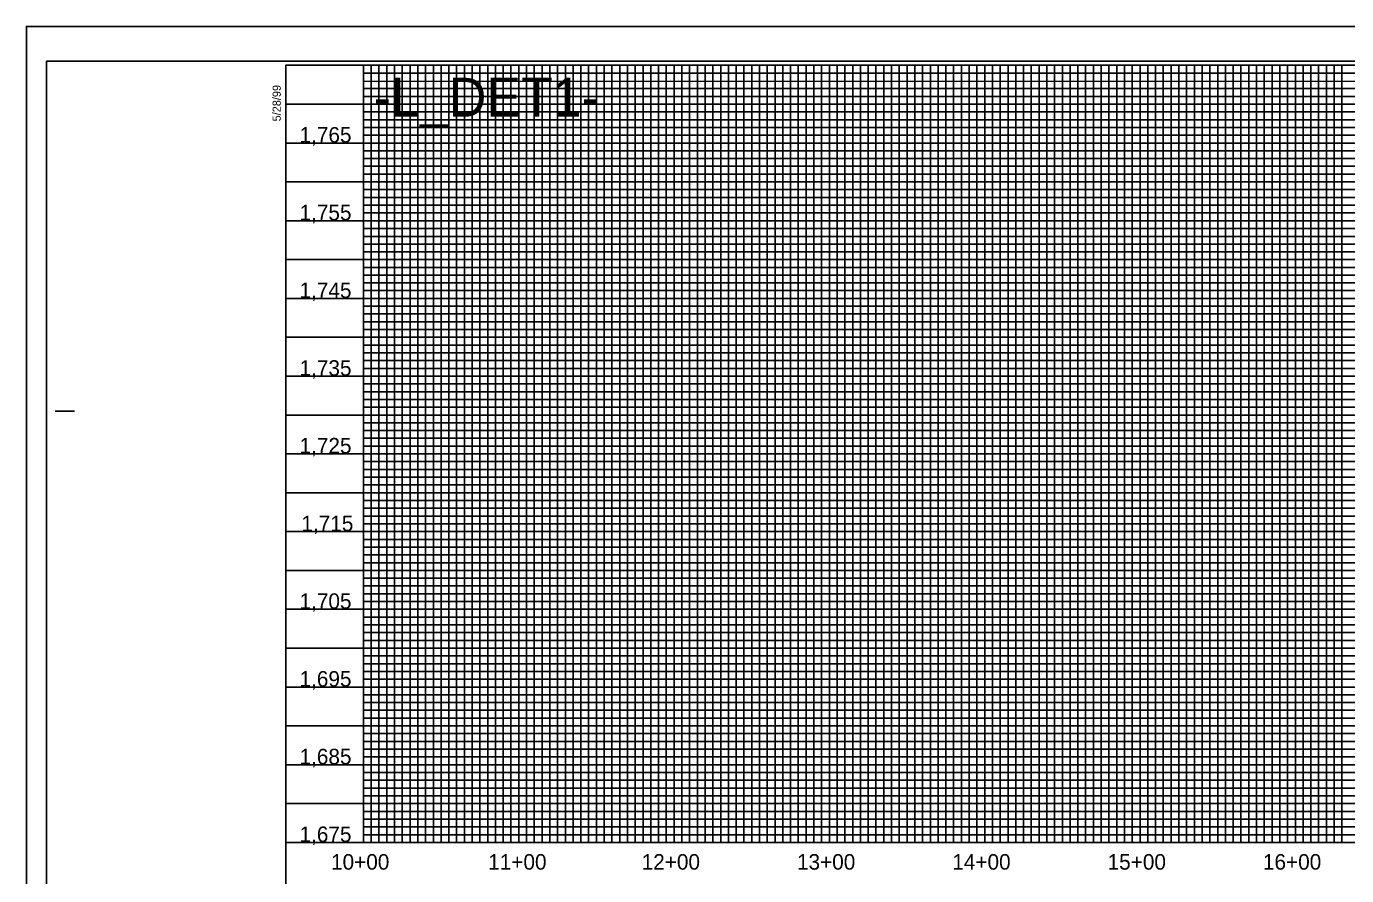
# Model space of a CAD drawing. Extents: x 505692 to 507376, y 438761 to 439861.
# Drawn here: x 505692 to 506542, y 439315 to 439861 of the extents above; entities that cross this region are included whole.
import ezdxf

# ---------------------------------------------------------------- set-up
doc = ezdxf.new("R2010")
doc.units = 0
for name, color, linetype in [('Exist Vertical Profile Vertical Axis Label', 7, 'Continuous'), ('Old_Level_1', 7, 'Continuous'), ('Prop Grid Mask', 7, 'Continuous'), ('Sheet Cutting Line CELL', 7, 'Continuous'), ('Sheet DOT Grid CELL', 7, 'Continuous'), ('Sheet Layout Profile Border Port 1', 7, 'Continuous'), ('Sheet Plot Border Inside CELL', 7, 'Continuous'), ('Sheet Plot Border Outside CELL', 7, 'Continuous'), ('Sheet Profile CELL', 7, 'Continuous'), ('Sheet Profile Grid Major CELL', 7, 'Continuous'), ('Sheet Profile Grid Middle CELL', 7, 'Continuous'), ('Sheet Profile Grid Minor CELL', 7, 'Continuous')]:
    doc.layers.add(name, color=color, linetype=linetype)

msp = doc.modelspace()

# ---------------------------------------------------------------- linework, layer by layer
at = {"layer": 'Prop Grid Mask'}
msp.add_lwpolyline([(506068.68, 439836.14), (505908.68, 439836.14), (505908.68, 439791.14), (506068.68, 439791.14)], close=True, dxfattribs=at)
at = {"layer": 'Sheet Cutting Line CELL'}
for p, q in [((507375.68, 439861.14), (505691.68, 439861.14)), ((505691.68, 439861.14), (505691.68, 438761.14))]:
    msp.add_line(p, q, dxfattribs=at)
at = {"layer": 'Sheet DOT Grid CELL'}
for p, q in [((505908.68, 439336.14), (505908.68, 439836.14)), ((505958.68, 439336.14), (505958.68, 439836.14)), ((506008.68, 439336.14), (506008.68, 439836.14)), ((506058.68, 439336.14), (506058.68, 439836.14)), ((506108.68, 439336.14), (506108.68, 439836.14)), ((506158.68, 439336.14), (506158.68, 439836.14)), ((506208.68, 439336.14), (506208.68, 439836.14)), ((506258.68, 439336.14), (506258.68, 439836.14)), ((506308.68, 439336.14), (506308.68, 439836.14)), ((506358.68, 439336.14), (506358.68, 439836.14)), ((506408.68, 439336.14), (506408.68, 439836.14)), ((506458.68, 439336.14), (506458.68, 439836.14)), ((506508.68, 439336.14), (506508.68, 439836.14)), ((507158.63, 439786.14), (505858.68, 439786.14)), ((507158.63, 439736.14), (505858.68, 439736.14)), ((507158.68, 439686.14), (505858.68, 439686.14)), ((507358.68, 439636.14), (505858.68, 439636.14)), ((507358.68, 439586.14), (505858.68, 439586.14)), ((507358.68, 439536.14), (505858.68, 439536.14)), ((507358.68, 439486.14), (505858.68, 439486.14)), ((507358.68, 439436.14), (505858.68, 439436.14)), ((507358.68, 439386.14), (505858.68, 439386.14))]:
    msp.add_line(p, q, dxfattribs=at)
at = {"layer": 'Sheet Layout Profile Border Port 1'}
msp.add_lwpolyline([(505908.68, 439836.14), (505908.68, 439336.14), (507108.68, 439336.14), (507108.68, 439486.14), (507108.68, 439636.14), (507108.68, 439836.14)], close=True, dxfattribs=at)
at = {"layer": 'Sheet Plot Border Inside CELL'}
msp.add_lwpolyline([(505704.68, 438783.59), (507371.18, 438783.59), (507371.18, 439838.69), (505704.68, 439838.69)], close=True, dxfattribs=at)
at = {"layer": 'Sheet Plot Border Outside CELL'}
msp.add_lwpolyline([(505691.68, 438761.14), (507375.68, 438761.14), (507375.68, 439861.14), (505691.68, 439861.14)], close=True, dxfattribs=at)
at = {"layer": 'Sheet Profile CELL'}
for p, q in [((505710.18, 439613.64), (505722.68, 439613.64)), ((505858.68, 439336.14), (507358.68, 439336.14))]:
    msp.add_line(p, q, dxfattribs=at)
msp.add_lwpolyline([(507358.68, 439836.14), (505858.68, 439836.14), (505858.68, 438786.14), (507358.68, 438786.14)], close=True, dxfattribs=at)
at = {"layer": 'Sheet Profile Grid Major CELL'}
for points in [[(505908.68, 439836.14), (505908.68, 439336.14), (505958.68, 439336.14), (505958.68, 439836.14), (506008.68, 439836.14), (506008.68, 439336.14), (506058.68, 439336.14), (506058.68, 439836.14), (506108.68, 439836.14), (506108.68, 439336.14), (506158.68, 439336.14), (506158.68, 439836.14), (506208.68, 439836.14), (506208.68, 439336.14), (506258.68, 439336.14), (506258.68, 439836.14), (506308.68, 439836.14), (506308.68, 439336.14), (506358.68, 439336.14), (506358.68, 439836.14), (506408.68, 439836.14), (506408.68, 439336.14), (506458.68, 439336.14), (506458.68, 439836.14), (506508.68, 439836.14), (506508.68, 439336.14), (506558.68, 439336.14)], [(505858.68, 439786.14), (507158.68, 439786.14)], [(507158.68, 439736.14), (505858.68, 439736.14), (505858.68, 439686.14), (507158.68, 439686.14)], [(507358.68, 439636.14), (505858.68, 439636.14), (505858.68, 439586.14), (507358.68, 439586.14)], [(507358.68, 439536.14), (505858.68, 439536.14), (505858.68, 439486.14), (507358.68, 439486.14)], [(507358.68, 439436.14), (505858.68, 439436.14), (505858.68, 439436.14), (505858.68, 439386.14), (507358.68, 439386.14)]]:
    msp.add_lwpolyline(points, dxfattribs=at)
at = {"layer": 'Sheet Profile Grid Middle CELL'}
msp.add_line((505858.68, 439811.14), (507158.63, 439811.14), dxfattribs=at)
for points in [[(505933.68, 439836.14), (505933.68, 439336.14), (505983.68, 439336.14), (505983.68, 439836.14), (506033.68, 439836.14), (506033.68, 439336.14), (506083.68, 439336.14), (506083.68, 439836.14), (506133.68, 439836.14), (506133.68, 439336.14), (506183.68, 439336.14), (506183.68, 439836.14), (506233.68, 439836.14), (506233.68, 439336.14), (506283.68, 439336.14), (506283.68, 439836.14), (506333.68, 439836.14), (506333.68, 439336.14), (506383.68, 439336.14), (506383.68, 439836.14), (506433.68, 439836.14), (506433.68, 439336.14), (506483.68, 439336.14), (506483.68, 439336.14), (506483.68, 439836.14), (506533.68, 439836.14), (506533.68, 439336.14), (506583.68, 439336.14)], [(507158.68, 439761.14), (505858.68, 439761.14), (505858.68, 439711.14), (507158.68, 439711.14)], [(507358.68, 439661.14), (505858.68, 439661.14), (505858.68, 439611.14), (507183.68, 439611.14)], [(507358.68, 439561.14), (505858.68, 439561.14), (505858.68, 439511.14), (507358.68, 439511.14)], [(507358.68, 439461.14), (505858.68, 439461.14), (505858.68, 439411.14), (507358.68, 439411.14)], [(507358.68, 439361.14), (505858.68, 439361.14)]]:
    msp.add_lwpolyline(points, dxfattribs=at)
at = {"layer": 'Sheet Profile Grid Minor CELL'}
for p, q in [((505908.68, 439831.14), (507158.68, 439831.14)), ((505908.68, 439826.14), (505908.68, 439826.14)), ((507158.68, 439826.14), (505908.68, 439825.79)), ((505908.68, 439821.14), (507158.68, 439821.14)), ((507158.63, 439701.14), (505908.68, 439701.14)), ((507158.68, 439696.14), (505908.68, 439696.14)), ((507158.68, 439691.14), (505908.68, 439691.14)), ((505908.68, 439681.14), (507158.68, 439681.14)), ((507158.68, 439676.14), (505908.68, 439676.14)), ((505908.68, 439671.14), (507308.68, 439671.14)), ((507308.68, 439651.14), (505908.68, 439651.14)), ((505908.68, 439646.14), (507308.68, 439646.14)), ((507308.68, 439626.14), (505908.68, 439626.14)), ((505908.68, 439621.14), (507308.68, 439621.14)), ((507308.68, 439601.14), (505908.68, 439601.14)), ((505908.68, 439596.14), (507308.68, 439596.14)), ((507308.68, 439591.14), (505908.68, 439591.14)), ((505908.68, 439581.14), (507308.68, 439581.14)), ((507308.68, 439576.14), (505908.68, 439576.14)), ((505908.68, 439571.14), (507308.68, 439571.14)), ((507308.68, 439566.14), (505908.68, 439566.14)), ((505908.68, 439556.14), (507308.68, 439556.14)), ((507308.68, 439551.14), (505908.68, 439551.14)), ((505908.68, 439546.14), (507308.68, 439546.14)), ((507308.68, 439541.14), (505908.68, 439541.14)), ((505908.68, 439531.14), (507308.68, 439531.14)), ((507308.68, 439526.14), (505908.68, 439526.14)), ((505908.68, 439521.14), (507308.68, 439521.14)), ((507308.68, 439516.14), (505908.68, 439516.14)), ((505908.68, 439506.14), (507308.68, 439506.14)), ((507308.68, 439501.14), (505908.68, 439501.14)), ((505908.68, 439496.14), (507308.68, 439496.14)), ((507308.68, 439491.14), (505908.68, 439491.14)), ((505908.68, 439481.14), (507308.68, 439481.14)), ((507308.68, 439476.14), (505908.68, 439476.14)), ((505908.68, 439471.14), (507308.68, 439471.14)), ((507308.68, 439466.14), (505908.68, 439466.14)), ((505908.68, 439456.14), (507308.68, 439456.14)), ((507308.68, 439451.14), (505908.68, 439451.14)), ((507308.68, 439446.14), (505908.68, 439446.14)), ((507308.68, 439441.14), (505908.68, 439441.14)), ((505908.68, 439431.14), (507308.68, 439431.14)), ((507308.68, 439426.14), (505908.68, 439426.14)), ((505908.68, 439421.14), (507308.68, 439421.14)), ((507308.68, 439416.14), (505908.68, 439416.14)), ((505908.68, 439406.14), (507308.68, 439406.14)), ((507308.68, 439401.14), (505908.68, 439401.14)), ((505908.68, 439396.14), (507308.68, 439396.14)), ((507308.68, 439391.14), (505908.68, 439391.14)), ((505908.68, 439381.14), (507308.68, 439381.14)), ((507308.68, 439376.14), (505908.68, 439376.14)), ((505908.68, 439371.14), (507308.68, 439371.14)), ((507308.68, 439366.14), (505908.68, 439366.14)), ((505908.68, 439356.14), (507308.68, 439356.14)), ((507308.68, 439351.14), (505908.68, 439351.14)), ((505908.68, 439346.14), (507308.68, 439346.14))]:
    msp.add_line(p, q, dxfattribs=at)
for points in [[(505913.68, 439836.14), (505913.68, 439336.14), (505918.68, 439336.14), (505918.68, 439836.14), (505923.68, 439836.14), (505923.68, 439336.14), (505928.68, 439336.14), (505928.68, 439836.14), (505938.68, 439836.14), (505938.68, 439336.14), (505943.68, 439336.14), (505943.68, 439836.14), (505948.68, 439836.14), (505948.68, 439336.14), (505953.68, 439336.14), (505963.68, 439336.14), (505968.68, 439336.14), (505968.68, 439836.14), (505973.68, 439836.14), (505973.68, 439336.14), (505978.68, 439336.14), (505978.68, 439836.14), (505988.68, 439836.14), (505988.68, 439336.14), (505993.68, 439336.14), (505993.68, 439836.14), (505998.68, 439836.14), (505998.68, 439336.14), (506003.68, 439336.14), (506003.68, 439836.14), (506013.68, 439836.14), (506013.68, 439336.14), (506018.68, 439336.14), (506018.68, 439836.14), (506023.68, 439836.14), (506023.68, 439336.14), (506028.68, 439336.14), (506028.68, 439836.14), (506038.68, 439836.14), (506038.68, 439336.14), (506043.68, 439336.14), (506043.68, 439836.14), (506048.68, 439836.14), (506048.68, 439336.14), (506053.68, 439336.14), (506053.68, 439836.14), (506063.68, 439836.14), (506063.68, 439336.14), (506068.68, 439336.14), (506068.68, 439836.14), (506073.68, 439836.14), (506073.68, 439336.14), (506078.68, 439336.14), (506078.68, 439836.14), (506088.68, 439836.14), (506088.68, 439336.14), (506093.68, 439336.14), (506093.68, 439836.14), (506098.68, 439836.14), (506098.68, 439336.14), (506103.68, 439336.14), (506103.68, 439836.14), (506113.68, 439836.14), (506113.68, 439336.14), (506118.68, 439336.14), (506118.68, 439836.14), (506123.68, 439836.14), (506123.68, 439336.14)], [(505953.68, 439336.14), (505953.68, 439836.14), (505963.68, 439836.14), (505963.68, 439336.14)], [(506123.68, 439336.14), (506128.68, 439336.14), (506128.68, 439836.14), (506138.68, 439836.14), (506138.68, 439336.14), (506143.68, 439336.14), (506143.68, 439836.14), (506148.68, 439836.14), (506148.68, 439336.14), (506153.68, 439336.14), (506153.68, 439836.14), (506163.68, 439836.14), (506163.68, 439336.14), (506168.68, 439336.14), (506168.68, 439836.14), (506173.68, 439836.14), (506173.68, 439336.14), (506178.68, 439336.14), (506178.68, 439836.14), (506188.68, 439836.14), (506188.68, 439336.14), (506193.68, 439336.14), (506193.68, 439836.14), (506198.68, 439836.14), (506198.68, 439336.14), (506203.68, 439336.14), (506203.68, 439836.14), (506213.68, 439836.14), (506213.68, 439336.14), (506218.68, 439336.14), (506218.68, 439836.14), (506223.68, 439836.14), (506223.68, 439336.14), (506228.68, 439336.14), (506228.68, 439836.14), (506238.68, 439836.14), (506238.68, 439336.14), (506243.68, 439336.14), (506243.68, 439836.14), (506248.68, 439836.14), (506248.68, 439336.14), (506253.68, 439336.14), (506253.68, 439836.14), (506263.68, 439836.14), (506263.68, 439336.14), (506268.68, 439336.14), (506268.68, 439836.14), (506273.68, 439836.14), (506273.68, 439336.14), (506278.68, 439336.14), (506278.68, 439836.14), (506288.68, 439836.14), (506288.68, 439336.14), (506293.68, 439336.14), (506293.68, 439836.14), (506298.68, 439836.14), (506298.68, 439336.14), (506303.68, 439336.14), (506303.68, 439836.14), (506313.68, 439836.14), (506313.68, 439336.14), (506318.68, 439336.14), (506318.68, 439836.14), (506323.68, 439836.14), (506323.68, 439336.14), (506328.68, 439336.14), (506328.68, 439836.14), (506338.68, 439836.14), (506338.68, 439336.14), (506343.68, 439336.14), (506343.68, 439836.14), (506348.68, 439836.14), (506348.68, 439336.14), (506353.68, 439336.14), (506353.68, 439836.14), (506363.68, 439836.14), (506363.68, 439336.14), (506368.68, 439336.14), (506368.68, 439836.14), (506373.68, 439836.14), (506373.68, 439336.14), (506378.68, 439336.14), (506378.68, 439836.14), (506388.68, 439836.14), (506388.68, 439336.14), (506393.68, 439336.14), (506393.68, 439836.14), (506398.68, 439836.14), (506398.68, 439336.14), (506403.68, 439336.14), (506403.68, 439836.14), (506413.68, 439836.14), (506413.68, 439336.14), (506418.68, 439336.14), (506418.68, 439836.14), (506423.68, 439836.14), (506423.68, 439336.14), (506428.68, 439336.14), (506428.68, 439836.14), (506438.68, 439836.14)], [(506438.68, 439836.14), (506438.68, 439336.14), (506443.68, 439336.14), (506443.68, 439836.14), (506448.68, 439836.14), (506448.68, 439336.14), (506453.68, 439336.14), (506453.68, 439836.14), (506463.68, 439836.14), (506463.68, 439336.14), (506468.68, 439336.14), (506468.68, 439836.14), (506473.68, 439836.14), (506473.68, 439336.14), (506478.68, 439336.14), (506478.68, 439836.14), (506488.68, 439836.14), (506488.68, 439336.14), (506493.68, 439336.14), (506493.68, 439836.14), (506498.68, 439836.14), (506498.68, 439336.14), (506503.68, 439336.14), (506503.68, 439836.14), (506513.68, 439836.14), (506513.68, 439336.14), (506518.68, 439336.14), (506518.68, 439836.14), (506523.68, 439836.14), (506523.68, 439336.14), (506528.68, 439336.14), (506528.68, 439836.14), (506538.68, 439836.14), (506538.68, 439336.14), (506543.68, 439336.14)], [(507158.68, 439816.14), (505908.68, 439816.14), (505908.68, 439806.14), (507158.68, 439806.14)], [(507158.63, 439801.14), (505908.68, 439801.14), (505908.68, 439796.14), (507158.68, 439796.14)], [(507158.68, 439791.14), (505908.68, 439791.14), (505908.68, 439781.14), (507158.68, 439781.14)], [(507158.68, 439776.14), (505908.68, 439776.14), (505908.68, 439771.14), (507158.68, 439771.14)], [(507158.68, 439766.14), (505908.68, 439766.14), (505908.68, 439756.14), (507158.68, 439756.14)], [(507158.68, 439751.14), (505908.68, 439751.14), (505908.68, 439746.14), (507158.68, 439746.14)], [(507158.68, 439741.14), (505908.68, 439741.14), (505908.68, 439731.14), (507158.68, 439731.14)], [(507158.68, 439726.04), (505908.78, 439726.04), (505908.78, 439721.14), (507158.68, 439721.14)], [(507158.68, 439716.14), (505908.68, 439716.14), (505908.68, 439706.14), (507158.68, 439706.14)], [(507308.68, 439666.14), (505908.68, 439666.14), (505908.68, 439656.14), (507308.68, 439656.14)], [(507308.68, 439641.14), (505908.68, 439641.14), (505908.68, 439631.14), (507308.68, 439631.14)], [(507308.68, 439616.14), (505908.68, 439616.14), (505908.68, 439606.14), (507308.68, 439606.14)], [(507308.68, 439341.14), (505908.68, 439341.14)]]:
    msp.add_lwpolyline(points, dxfattribs=at)

# ---------------------------------------------------------------- texts
at = {"layer": 'Exist Vertical Profile Vertical Axis Label'}
for s, p in [('1,765', (505867.53, 439786.39)), ('1,765', (505867.53, 439786.39)), ('1,765', (505867.53, 439786.39)), ('1,765', (505867.53, 439786.39)), ('1,755', (505867.53, 439736.39)), ('1,755', (505867.53, 439736.39)), ('1,755', (505867.53, 439736.39)), ('1,755', (505867.53, 439736.39)), ('1,745', (505867.53, 439686.39)), ('1,745', (505867.53, 439686.39)), ('1,745', (505867.53, 439686.39)), ('1,745', (505867.53, 439686.39)), ('1,735', (505867.53, 439636.39)), ('1,735', (505867.53, 439636.39)), ('1,735', (505867.53, 439636.39)), ('1,735', (505867.53, 439636.39)), ('1,725', (505867.53, 439586.39)), ('1,725', (505867.53, 439586.39)), ('1,725', (505867.53, 439586.39)), ('1,725', (505867.53, 439586.39)), ('1,715', (505868.73, 439536.39)), ('1,715', (505868.73, 439536.39)), ('1,715', (505868.73, 439536.39)), ('1,715', (505868.73, 439536.39)), ('1,705', (505867.53, 439486.39)), ('1,705', (505867.53, 439486.39)), ('1,705', (505867.53, 439486.39)), ('1,705', (505867.53, 439486.39)), ('1,695', (505867.53, 439436.39)), ('1,695', (505867.53, 439436.39)), ('1,695', (505867.53, 439436.39)), ('1,695', (505867.53, 439436.39)), ('1,685', (505867.53, 439386.39)), ('1,685', (505867.53, 439386.39)), ('1,685', (505867.53, 439386.39)), ('1,685', (505867.53, 439386.39)), ('1,675', (505867.53, 439336.39)), ('1,675', (505867.53, 439336.39)), ('1,675', (505867.53, 439336.39)), ('1,675', (505867.53, 439336.39)), ('10+00', (505887.81, 439318.64)), ('11+00', (505989, 439318.64)), ('12+00', (506087.81, 439318.64)), ('13+00', (506187.81, 439318.64)), ('14+00', (506287.81, 439318.64)), ('15+00', (506387.81, 439318.64)), ('16+00', (506487.81, 439318.64))]:
    msp.add_text(s, height=10, dxfattribs=at).set_placement(p)
at = {"layer": 'Old_Level_1'}
msp.add_text('-L_DET1-', height=25, dxfattribs=at).set_placement((505915.37, 439803.11))
at = {"layer": 'Sheet Profile CELL'}
msp.add_text('5/28/99', height=5.25, rotation=90, dxfattribs=at).set_placement((505855.44, 439800.06))

doc.saveas('drawing.dxf')
